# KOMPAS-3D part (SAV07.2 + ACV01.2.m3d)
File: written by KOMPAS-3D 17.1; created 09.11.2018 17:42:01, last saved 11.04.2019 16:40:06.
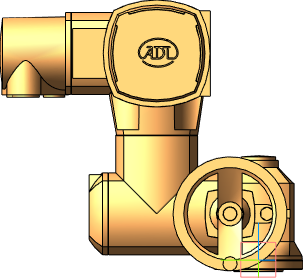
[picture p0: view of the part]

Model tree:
1. Операция без истории:3

Referenced files: sarv07_2_small.SLDASM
